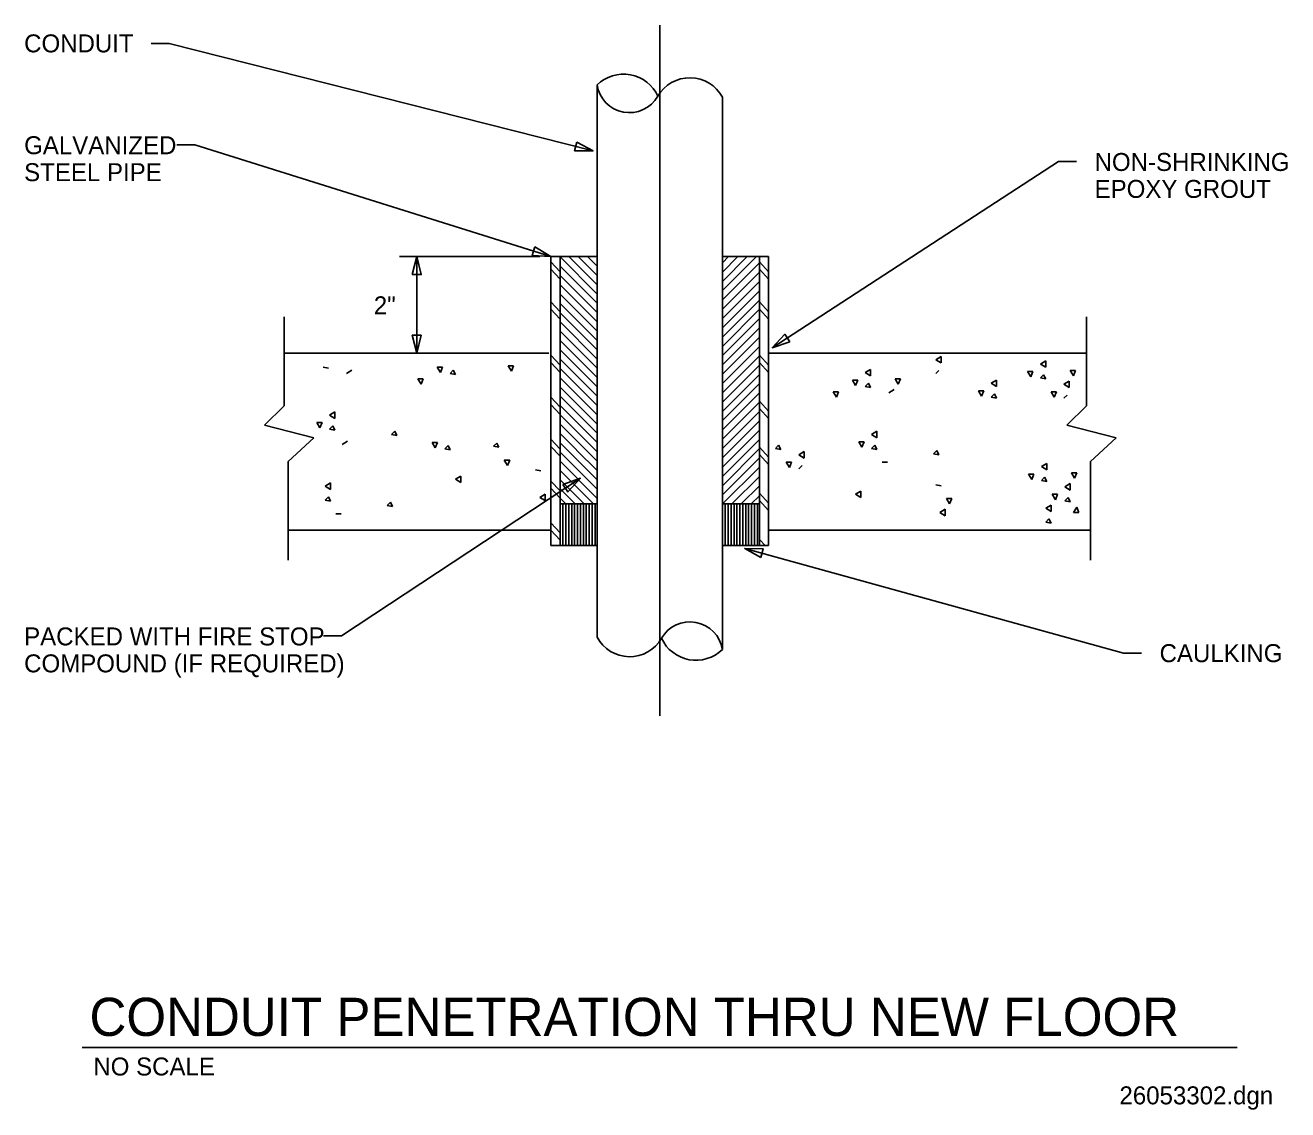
# Model space of a CAD drawing. Extents: x 10301.9 to 10348.7, y 10085.4 to 10125.7.
import ezdxf

# ---------------------------------------------------------------- set-up
doc = ezdxf.new("R2010")
doc.units = 0
for name, color, linetype in [('G-ANNO-TEXT', 7, 'Continuous'), ('Level 3', 7, 'Continuous'), ('Level 52', 7, 'Continuous'), ('Level 60', 7, 'Continuous'), ('Level 61', 7, 'Continuous'), ('Level 62', 7, 'Continuous'), ('Level 63', 7, 'Continuous')]:
    doc.layers.add(name, color=color, linetype=linetype)

msp = doc.modelspace()

# ---------------------------------------------------------------- linework, layer by layer
at = {"layer": 'G-ANNO-TEXT'}
for p, q in [((10308.164, 10121.236), (10321.368, 10117.083)), ((10313.603, 10103.007), (10322.465, 10108.856))]:
    msp.add_line(p, q, dxfattribs=at)
for points in [[(10320.782, 10117.442), (10321.368, 10117.083), (10320.682, 10117.124)], [(10316.231, 10116.417), (10316.398, 10117.083), (10316.564, 10116.417)], [(10316.231, 10116.417), (10316.398, 10117.083), (10316.564, 10116.417)], [(10316.564, 10114.162), (10316.398, 10113.495), (10316.231, 10114.162)], [(10321.817, 10108.628), (10322.465, 10108.856), (10322.001, 10108.35)]]:
    msp.add_lwpolyline(points, close=True, dxfattribs=at)
at = {"layer": 'Level 52'}
msp.add_line((10303.985, 10087.727), (10346.832, 10087.727), dxfattribs=at)
at = {"layer": 'Level 60'}
for p, q in [((10321.71, 10116.514), (10321.368, 10116.884)), ((10321.71, 10117.069), (10323.085, 10115.694)), ((10322.04, 10117.083), (10323.085, 10116.039)), ((10322.385, 10117.083), (10323.085, 10116.384)), ((10322.73, 10117.083), (10323.085, 10116.729)), ((10323.075, 10117.083), (10323.085, 10117.073)), ((10327.732, 10116.854), (10327.961, 10117.083)), ((10327.732, 10116.509), (10328.306, 10117.083)), ((10327.732, 10116.164), (10328.651, 10117.083)), ((10327.732, 10115.82), (10328.996, 10117.083)), ((10327.732, 10115.475), (10329.106, 10116.85)), ((10329.448, 10116.514), (10329.106, 10116.884)), ((10321.71, 10116.245), (10321.368, 10116.615)), ((10321.71, 10116.724), (10323.085, 10115.35)), ((10321.71, 10116.38), (10323.085, 10115.005)), ((10327.732, 10115.13), (10329.106, 10116.505)), ((10329.448, 10116.245), (10329.106, 10116.615)), ((10321.71, 10116.035), (10323.085, 10114.66)), ((10327.732, 10114.786), (10329.106, 10116.16)), ((10321.71, 10115.69), (10323.085, 10114.316)), ((10327.732, 10114.441), (10329.106, 10115.815)), ((10327.732, 10114.096), (10329.106, 10115.471)), ((10321.71, 10115.035), (10321.368, 10115.404)), ((10321.71, 10114.766), (10321.368, 10115.135)), ((10321.71, 10115.345), (10323.085, 10113.971)), ((10321.71, 10115.001), (10323.085, 10113.626)), ((10327.732, 10113.752), (10329.106, 10115.126)), ((10329.448, 10115.035), (10329.106, 10115.404)), ((10329.448, 10114.766), (10329.106, 10115.135)), ((10321.71, 10114.656), (10323.085, 10113.281)), ((10327.732, 10113.407), (10329.106, 10114.781)), ((10321.71, 10114.311), (10323.085, 10112.937)), ((10327.732, 10113.062), (10329.106, 10114.437)), ((10327.732, 10112.717), (10329.106, 10114.092)), ((10321.71, 10113.967), (10323.085, 10112.592)), ((10321.71, 10113.622), (10323.085, 10112.247)), ((10327.732, 10112.373), (10329.106, 10113.747)), ((10321.71, 10113.051), (10321.368, 10113.421)), ((10321.71, 10112.782), (10321.368, 10113.152)), ((10321.71, 10113.277), (10323.085, 10111.903)), ((10327.732, 10112.028), (10329.106, 10113.402)), ((10329.448, 10113.051), (10329.106, 10113.421)), ((10329.448, 10112.782), (10329.106, 10113.152)), ((10335.843, 10113.374), (10335.645, 10113.255)), ((10335.645, 10113.255), (10335.843, 10113.136)), ((10335.843, 10113.136), (10335.843, 10113.374)), ((10339.726, 10113.215), (10339.527, 10113.096)), ((10339.527, 10113.096), (10339.726, 10112.977)), ((10339.726, 10112.977), (10339.726, 10113.215)), ((10312.923, 10112.982), (10313.121, 10112.943)), ((10313.993, 10112.863), (10313.795, 10112.744)), ((10317.155, 10112.981), (10317.274, 10112.782)), ((10317.353, 10112.981), (10317.155, 10112.981)), ((10317.274, 10112.782), (10317.353, 10112.981)), ((10317.749, 10112.862), (10317.63, 10112.743)), ((10317.63, 10112.743), (10317.829, 10112.703)), ((10317.829, 10112.703), (10317.749, 10112.862)), ((10319.991, 10113.023), (10319.793, 10113.023)), ((10319.793, 10113.023), (10319.912, 10112.825)), ((10319.912, 10112.825), (10319.991, 10113.023)), ((10321.71, 10112.932), (10323.085, 10111.558)), ((10327.732, 10111.683), (10329.106, 10113.058)), ((10327.732, 10111.338), (10329.106, 10112.713)), ((10333.228, 10112.898), (10333.029, 10112.779)), ((10333.029, 10112.779), (10333.228, 10112.66)), ((10333.228, 10112.66), (10333.228, 10112.898)), ((10335.763, 10112.858), (10335.645, 10112.739)), ((10339.25, 10112.819), (10339.052, 10112.819)), ((10339.052, 10112.819), (10339.171, 10112.62)), ((10339.171, 10112.62), (10339.25, 10112.819)), ((10339.646, 10112.7), (10339.527, 10112.581)), ((10339.726, 10112.541), (10339.646, 10112.7)), ((10340.835, 10112.858), (10340.637, 10112.858)), ((10340.637, 10112.858), (10340.756, 10112.66)), ((10340.756, 10112.66), (10340.835, 10112.858)), ((10316.64, 10112.544), (10316.442, 10112.544)), ((10316.442, 10112.544), (10316.561, 10112.346)), ((10316.561, 10112.346), (10316.64, 10112.544)), ((10321.71, 10112.588), (10323.085, 10111.213)), ((10321.71, 10112.243), (10323.085, 10110.868)), ((10327.732, 10110.994), (10329.106, 10112.368)), ((10332.752, 10112.501), (10332.554, 10112.501)), ((10332.554, 10112.501), (10332.673, 10112.303)), ((10332.673, 10112.303), (10332.752, 10112.501)), ((10333.148, 10112.383), (10333.029, 10112.264)), ((10333.029, 10112.264), (10333.228, 10112.224)), ((10333.228, 10112.224), (10333.148, 10112.383)), ((10334.337, 10112.541), (10334.139, 10112.541)), ((10334.139, 10112.541), (10334.258, 10112.343)), ((10334.258, 10112.343), (10334.337, 10112.541)), ((10337.903, 10112.501), (10337.705, 10112.383)), ((10337.705, 10112.383), (10337.903, 10112.264)), ((10337.903, 10112.264), (10337.903, 10112.501)), ((10339.527, 10112.581), (10339.726, 10112.541)), ((10340.597, 10112.462), (10340.399, 10112.343)), ((10340.399, 10112.343), (10340.597, 10112.224)), ((10340.597, 10112.224), (10340.597, 10112.462)), ((10321.71, 10111.496), (10321.368, 10111.865)), ((10321.71, 10111.898), (10323.085, 10110.524)), ((10327.732, 10110.649), (10329.106, 10112.024)), ((10329.448, 10111.343), (10329.106, 10111.713)), ((10331.841, 10112.065), (10331.96, 10111.867)), ((10332.039, 10112.065), (10331.841, 10112.065)), ((10331.96, 10111.867), (10332.039, 10112.065)), ((10334.099, 10112.145), (10333.901, 10112.026)), ((10337.427, 10112.105), (10337.229, 10112.105)), ((10337.229, 10112.105), (10337.348, 10111.907)), ((10337.348, 10111.907), (10337.427, 10112.105)), ((10337.824, 10111.986), (10337.705, 10111.867)), ((10337.705, 10111.867), (10337.903, 10111.828)), ((10337.903, 10111.828), (10337.824, 10111.986)), ((10339.924, 10112.065), (10340.043, 10111.867)), ((10340.122, 10112.065), (10339.924, 10112.065)), ((10340.043, 10111.867), (10340.122, 10112.065)), ((10340.518, 10111.946), (10340.399, 10111.828)), ((10313.359, 10111.317), (10313.161, 10111.198)), ((10313.359, 10111.079), (10313.359, 10111.317)), ((10321.71, 10111.227), (10321.368, 10111.596)), ((10321.71, 10111.554), (10323.085, 10110.179)), ((10327.732, 10110.304), (10329.106, 10111.679)), ((10327.732, 10109.96), (10329.106, 10111.334)), ((10329.448, 10111.074), (10329.106, 10111.444)), ((10312.685, 10110.921), (10312.804, 10110.722)), ((10312.883, 10110.921), (10312.685, 10110.921)), ((10312.804, 10110.722), (10312.883, 10110.921)), ((10313.161, 10111.198), (10313.359, 10111.079)), ((10313.28, 10110.802), (10313.161, 10110.683)), ((10313.359, 10110.643), (10313.28, 10110.802)), ((10321.71, 10111.209), (10323.085, 10109.834)), ((10321.71, 10110.864), (10323.085, 10109.49)), ((10327.732, 10109.615), (10329.106, 10110.989)), ((10313.161, 10110.683), (10313.359, 10110.643)), ((10315.578, 10110.604), (10315.459, 10110.485)), ((10315.459, 10110.485), (10315.657, 10110.445)), ((10315.657, 10110.445), (10315.578, 10110.604)), ((10321.71, 10109.94), (10321.368, 10110.31)), ((10321.71, 10110.519), (10322.322, 10109.907)), ((10327.732, 10109.27), (10329.106, 10110.645)), ((10327.732, 10108.925), (10329.106, 10110.3)), ((10333.465, 10110.599), (10333.267, 10110.48)), ((10333.267, 10110.48), (10333.465, 10110.361)), ((10333.465, 10110.361), (10333.465, 10110.599)), ((10313.833, 10110.229), (10313.635, 10110.11)), ((10316.963, 10110.189), (10317.082, 10109.991)), ((10317.161, 10110.189), (10316.963, 10110.189)), ((10317.082, 10109.991), (10317.161, 10110.189)), ((10317.558, 10110.07), (10317.439, 10109.951)), ((10317.439, 10109.951), (10317.637, 10109.912)), ((10317.637, 10109.912), (10317.558, 10110.07)), ((10319.368, 10110.163), (10319.249, 10110.044)), ((10319.249, 10110.044), (10319.447, 10110.004)), ((10319.447, 10110.004), (10319.368, 10110.163)), ((10321.71, 10109.671), (10321.368, 10110.041)), ((10321.71, 10110.175), (10323.085, 10108.8)), ((10321.71, 10109.83), (10323.085, 10108.455)), ((10322.325, 10109.904), (10323.085, 10109.145)), ((10327.732, 10108.581), (10329.106, 10109.955)), ((10329.448, 10109.635), (10329.106, 10110.005)), ((10329.82, 10110.083), (10329.701, 10109.964)), ((10329.701, 10109.964), (10329.899, 10109.925)), ((10329.899, 10109.925), (10329.82, 10110.083)), ((10330.771, 10109.845), (10330.573, 10109.726)), ((10330.771, 10109.608), (10330.771, 10109.845)), ((10332.99, 10110.202), (10332.792, 10110.202)), ((10332.792, 10110.202), (10332.911, 10110.004)), ((10332.911, 10110.004), (10332.99, 10110.202)), ((10333.386, 10110.083), (10333.267, 10109.964)), ((10333.267, 10109.964), (10333.465, 10109.925)), ((10333.465, 10109.925), (10333.386, 10110.083)), ((10335.684, 10109.885), (10335.565, 10109.766)), ((10335.763, 10109.726), (10335.684, 10109.885)), ((10319.645, 10109.529), (10319.764, 10109.331)), ((10319.843, 10109.529), (10319.645, 10109.529)), ((10319.764, 10109.331), (10319.843, 10109.529)), ((10321.71, 10109.485), (10323.085, 10108.111)), ((10327.732, 10108.236), (10329.106, 10109.611)), ((10329.448, 10109.366), (10329.106, 10109.736)), ((10330.296, 10109.449), (10330.097, 10109.449)), ((10330.097, 10109.449), (10330.216, 10109.251)), ((10330.216, 10109.251), (10330.296, 10109.449)), ((10330.573, 10109.726), (10330.771, 10109.608)), ((10333.862, 10109.449), (10333.663, 10109.449)), ((10335.565, 10109.766), (10335.763, 10109.726)), ((10339.765, 10109.409), (10339.567, 10109.29)), ((10339.765, 10109.171), (10339.765, 10109.409)), ((10318.03, 10108.937), (10317.832, 10108.818)), ((10318.03, 10108.7), (10318.03, 10108.937)), ((10320.804, 10109.175), (10321.002, 10109.136)), ((10321.71, 10109.14), (10322.949, 10107.901)), ((10327.742, 10107.901), (10329.106, 10109.266)), ((10328.087, 10107.901), (10329.106, 10108.921)), ((10330.692, 10109.33), (10330.573, 10109.211)), ((10339.092, 10109.013), (10339.21, 10108.815)), ((10339.29, 10109.013), (10339.092, 10109.013)), ((10339.21, 10108.815), (10339.29, 10109.013)), ((10339.567, 10109.29), (10339.765, 10109.171)), ((10339.686, 10108.894), (10339.567, 10108.775)), ((10339.765, 10108.735), (10339.686, 10108.894)), ((10340.676, 10109.052), (10340.795, 10108.854)), ((10340.875, 10109.052), (10340.676, 10109.052)), ((10340.795, 10108.854), (10340.875, 10109.052)), ((10313.199, 10108.683), (10313.001, 10108.564)), ((10313.001, 10108.564), (10313.199, 10108.445)), ((10313.199, 10108.445), (10313.199, 10108.683)), ((10317.832, 10108.818), (10318.03, 10108.7)), ((10321.71, 10108.385), (10321.368, 10108.754)), ((10321.71, 10108.116), (10321.368, 10108.485)), ((10321.71, 10108.796), (10322.605, 10107.901)), ((10321.71, 10108.462), (10322.271, 10107.901)), ((10328.431, 10107.901), (10329.106, 10108.576)), ((10335.645, 10108.616), (10335.843, 10108.577)), ((10339.567, 10108.775), (10339.765, 10108.735)), ((10340.637, 10108.656), (10340.439, 10108.537)), ((10340.439, 10108.537), (10340.637, 10108.418)), ((10340.637, 10108.418), (10340.637, 10108.656)), ((10313.12, 10108.167), (10313.001, 10108.048)), ((10313.001, 10108.048), (10313.199, 10108.009)), ((10313.199, 10108.009), (10313.12, 10108.167)), ((10315.418, 10107.969), (10315.299, 10107.85)), ((10315.497, 10107.81), (10315.418, 10107.969)), ((10321.161, 10108.263), (10320.962, 10108.145)), ((10320.962, 10108.145), (10321.161, 10108.026)), ((10321.161, 10108.026), (10321.161, 10108.263)), ((10321.71, 10108.114), (10321.922, 10107.901)), ((10328.805, 10107.901), (10329.106, 10108.203)), ((10329.448, 10107.927), (10329.106, 10108.297)), ((10329.448, 10107.658), (10329.106, 10108.028)), ((10332.871, 10108.379), (10332.673, 10108.26)), ((10332.673, 10108.26), (10332.871, 10108.141)), ((10332.871, 10108.141), (10332.871, 10108.379)), ((10336.041, 10108.101), (10336.16, 10107.903)), ((10336.239, 10108.101), (10336.041, 10108.101)), ((10336.16, 10107.903), (10336.239, 10108.101)), ((10340.161, 10108.26), (10339.963, 10108.26)), ((10339.963, 10108.26), (10340.082, 10108.061)), ((10340.082, 10108.061), (10340.161, 10108.26)), ((10340.558, 10108.141), (10340.439, 10108.022)), ((10340.439, 10108.022), (10340.637, 10107.982)), ((10340.637, 10107.982), (10340.558, 10108.141)), ((10313.595, 10107.533), (10313.397, 10107.533)), ((10315.299, 10107.85), (10315.497, 10107.81)), ((10321.71, 10107.901), (10321.71, 10106.362)), ((10323.085, 10106.362), (10323.085, 10107.901)), ((10327.732, 10106.362), (10327.732, 10107.901)), ((10329.106, 10107.901), (10329.106, 10106.362)), ((10336.001, 10107.705), (10335.803, 10107.586)), ((10335.803, 10107.586), (10336.001, 10107.467)), ((10336.001, 10107.467), (10336.001, 10107.705)), ((10339.924, 10107.863), (10339.726, 10107.744)), ((10339.726, 10107.744), (10339.924, 10107.625)), ((10339.924, 10107.625), (10339.924, 10107.863)), ((10340.875, 10107.784), (10340.756, 10107.586)), ((10340.756, 10107.586), (10340.954, 10107.586)), ((10340.954, 10107.586), (10340.875, 10107.784)), ((10321.71, 10106.829), (10321.368, 10107.199)), ((10339.844, 10107.348), (10339.726, 10107.229)), ((10339.726, 10107.229), (10339.924, 10107.189)), ((10339.924, 10107.189), (10339.844, 10107.348)), ((10321.71, 10106.56), (10321.368, 10106.93)), ((10329.316, 10106.362), (10329.106, 10106.589)), ((10321.71, 10106.362), (10323.085, 10106.362)), ((10329.106, 10106.362), (10327.732, 10106.362))]:
    msp.add_line(p, q, dxfattribs=at)
at = {"layer": 'Level 61'}
for p, q in [((10311.473, 10113.495), (10321.293, 10113.495)), ((10341.233, 10113.495), (10329.448, 10113.495)), ((10321.819, 10107.901), (10321.819, 10106.362)), ((10321.927, 10107.901), (10321.927, 10106.362)), ((10322.035, 10107.901), (10322.035, 10106.362)), ((10322.144, 10107.901), (10322.144, 10106.362)), ((10322.252, 10107.901), (10322.252, 10106.362)), ((10322.36, 10107.901), (10322.36, 10106.362)), ((10322.469, 10107.901), (10322.469, 10106.362)), ((10322.577, 10107.901), (10322.577, 10106.362)), ((10322.685, 10107.901), (10322.685, 10106.362)), ((10322.794, 10107.901), (10322.794, 10106.362)), ((10322.902, 10107.901), (10322.902, 10106.362)), ((10323.01, 10107.901), (10323.01, 10106.362)), ((10327.84, 10106.362), (10327.84, 10107.901)), ((10327.949, 10106.362), (10327.949, 10107.901)), ((10328.057, 10106.362), (10328.057, 10107.901)), ((10328.165, 10106.362), (10328.165, 10107.901)), ((10328.274, 10106.362), (10328.274, 10107.901)), ((10328.382, 10106.362), (10328.382, 10107.901)), ((10328.49, 10106.362), (10328.49, 10107.901)), ((10328.599, 10106.362), (10328.599, 10107.901)), ((10328.707, 10106.362), (10328.707, 10107.901)), ((10328.815, 10106.362), (10328.815, 10107.901)), ((10328.924, 10106.362), (10328.924, 10107.901)), ((10329.032, 10106.362), (10329.032, 10107.901)), ((10321.368, 10106.934), (10311.623, 10106.934)), ((10341.384, 10106.934), (10329.448, 10106.934))]:
    msp.add_line(p, q, dxfattribs=at)
for points in [[(10323.085, 10107.901), (10321.71, 10107.901), (10321.71, 10106.362), (10323.085, 10106.362)], [(10329.106, 10107.901), (10327.732, 10107.901), (10327.732, 10106.362), (10329.106, 10106.362)]]:
    msp.add_lwpolyline(points, close=True, dxfattribs=at)
at = {"layer": 'Level 62'}
for p, q in [((10323.085, 10123.453), (10323.085, 10102.956)), ((10327.732, 10122.997), (10327.732, 10102.5)), ((10321.71, 10117.083), (10321.368, 10117.083)), ((10321.368, 10117.083), (10321.368, 10106.362)), ((10321.71, 10117.083), (10323.085, 10117.083)), ((10321.71, 10117.083), (10321.71, 10106.362)), ((10329.448, 10117.083), (10327.732, 10117.083)), ((10329.106, 10117.083), (10329.106, 10106.362)), ((10329.448, 10117.083), (10329.448, 10106.362)), ((10321.368, 10106.362), (10323.085, 10106.362)), ((10329.448, 10106.362), (10327.732, 10106.362))]:
    msp.add_line(p, q, dxfattribs=at)
for centre, radius, start, end in [((10324.066, 10122.452), 1.401, 24.5828, 134.427), ((10324.286, 10123.64), 1.216, 188.8535, 330.1563), ((10326.526, 10122.351), 1.369, 28.1692, 150.0111), ((10326.531, 10102.313), 1.216, 8.8535, 150.1563), ((10324.291, 10103.602), 1.369, 208.1692, 330.0111), ((10326.751, 10103.501), 1.401, 204.5828, 314.427)]:
    msp.add_arc(centre, radius, start, end, dxfattribs=at)
at = {"layer": 'Level 63'}
for p, q in [((10325.408, 10100.039), (10325.408, 10125.669)), ((10306.544, 10124.996), (10307.211, 10124.996)), ((10307.211, 10124.996), (10322.936, 10121.007)), ((10307.498, 10121.236), (10308.164, 10121.236)), ((10340.204, 10120.616), (10329.58, 10113.698)), ((10340.871, 10120.616), (10340.204, 10120.616)), ((10320.968, 10117.083), (10315.751, 10117.083)), ((10316.398, 10117.083), (10316.398, 10113.495)), ((10311.473, 10114.852), (10311.473, 10111.55)), ((10341.233, 10114.852), (10341.233, 10111.55)), ((10311.473, 10111.55), (10310.745, 10110.831)), ((10341.233, 10111.55), (10340.506, 10110.831)), ((10310.745, 10110.831), (10312.581, 10110.352)), ((10340.506, 10110.831), (10342.341, 10110.352)), ((10312.581, 10110.352), (10311.623, 10109.474)), ((10342.341, 10110.352), (10341.384, 10109.474)), ((10311.623, 10109.474), (10311.623, 10105.819)), ((10341.384, 10109.474), (10341.384, 10105.819)), ((10342.616, 10102.365), (10328.561, 10106.251)), ((10312.936, 10103.007), (10313.603, 10103.007)), ((10343.282, 10102.365), (10342.616, 10102.365))]:
    msp.add_line(p, q, dxfattribs=at)
for points in [[(10322.331, 10121.333), (10322.936, 10121.007), (10322.249, 10121.01)], [(10330.23, 10113.922), (10329.58, 10113.698), (10330.048, 10114.202)], [(10329.159, 10105.913), (10328.561, 10106.251), (10329.248, 10106.234)]]:
    msp.add_lwpolyline(points, close=True, dxfattribs=at)

# ---------------------------------------------------------------- texts
at = {"layer": 'Level 3'}
msp.add_text('26053302.dgn', height=0.66667, dxfattribs=at).set_placement((10342.46, 10085.621))
at = {"layer": 'Level 52'}
for s, height, p in [('CONDUIT PENETRATION THRU NEW FLOOR', 1.41667, (10304.258, 10088.16)), ('NO SCALE', 0.6667, (10304.402, 10086.692))]:
    msp.add_text(s, height=height, dxfattribs=at).set_placement(p)
at = {"layer": 'Level 63'}
for s, height, p in [('CONDUIT', 0.6667, (10301.835, 10124.662)), ('GALVANIZED ', 0.66667, (10301.835, 10120.882)), ('NON-SHRINKING', 0.66667, (10341.538, 10120.261)), ('STEEL PIPE', 0.6667, (10301.835, 10119.882)), ('EPOXY GROUT', 0.66667, (10341.538, 10119.261)), ('2"', 0.6667, (10314.804, 10114.94)), ('PACKED WITH FIRE STOP', 0.66667, (10301.835, 10102.653)), ('COMPOUND (IF REQUIRED)', 0.66667, (10301.835, 10101.653)), ('CAULKING', 0.6667, (10343.949, 10102.032))]:
    msp.add_text(s, height=height, dxfattribs=at).set_placement(p)

doc.saveas('drawing.dxf')
